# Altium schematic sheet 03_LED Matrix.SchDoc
size 772 x 495 mm
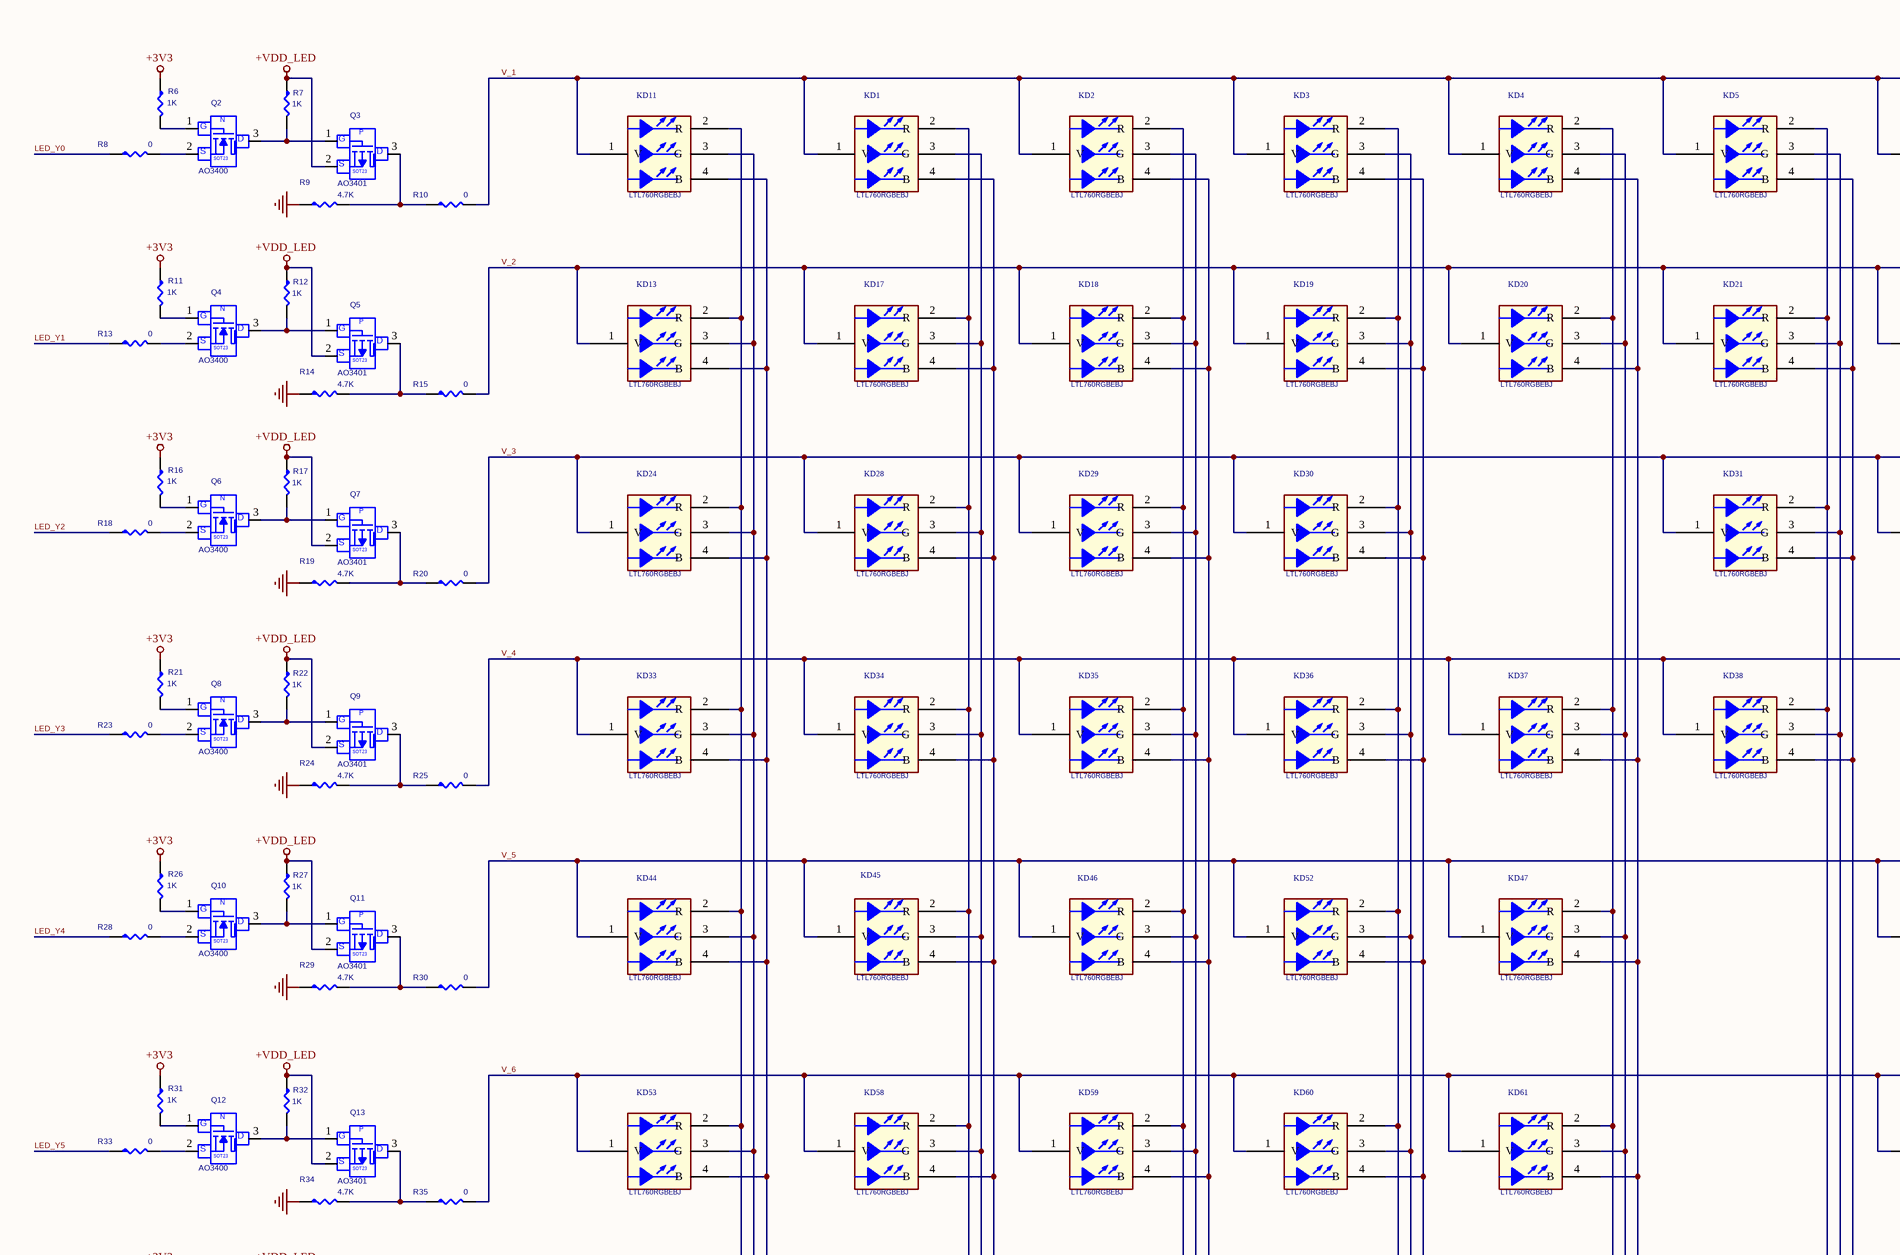
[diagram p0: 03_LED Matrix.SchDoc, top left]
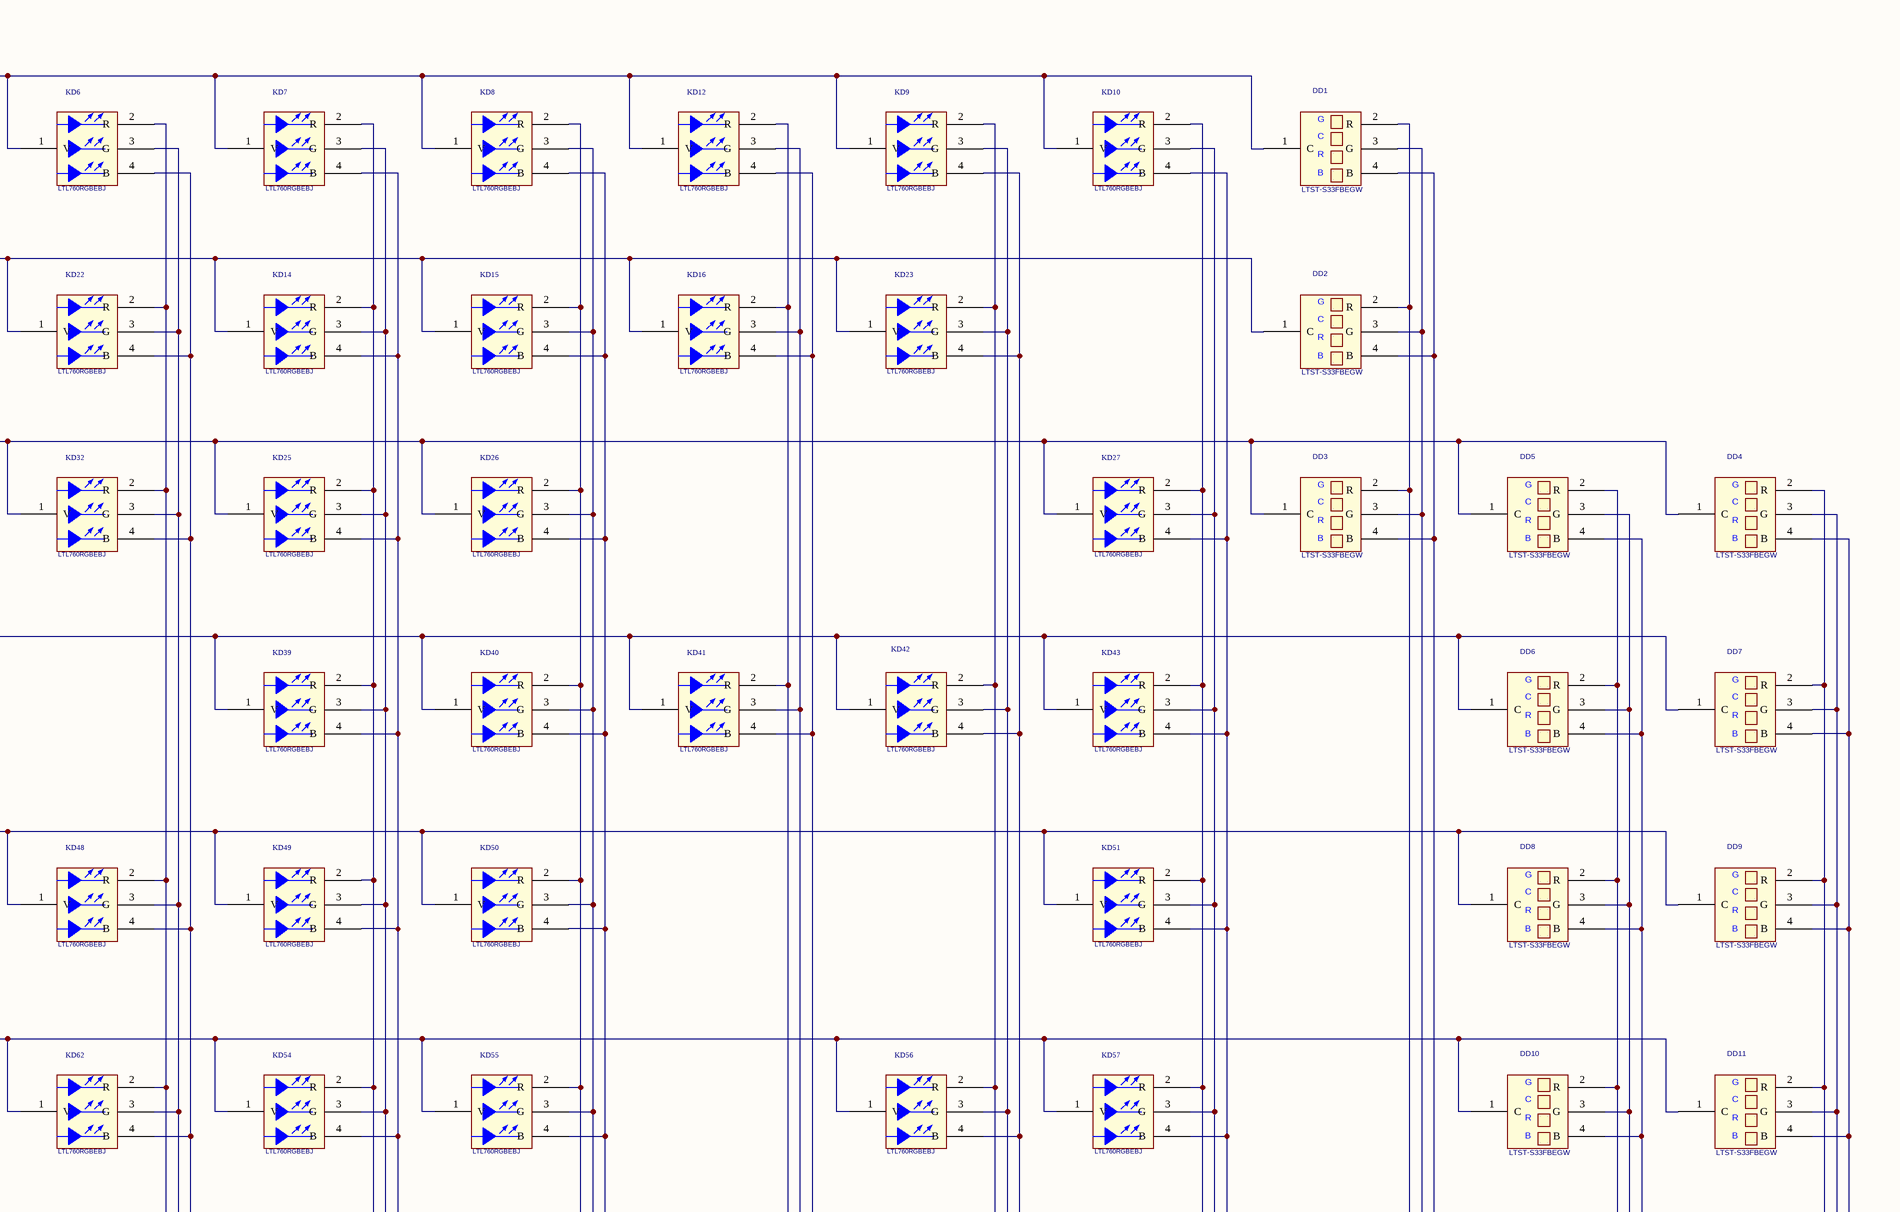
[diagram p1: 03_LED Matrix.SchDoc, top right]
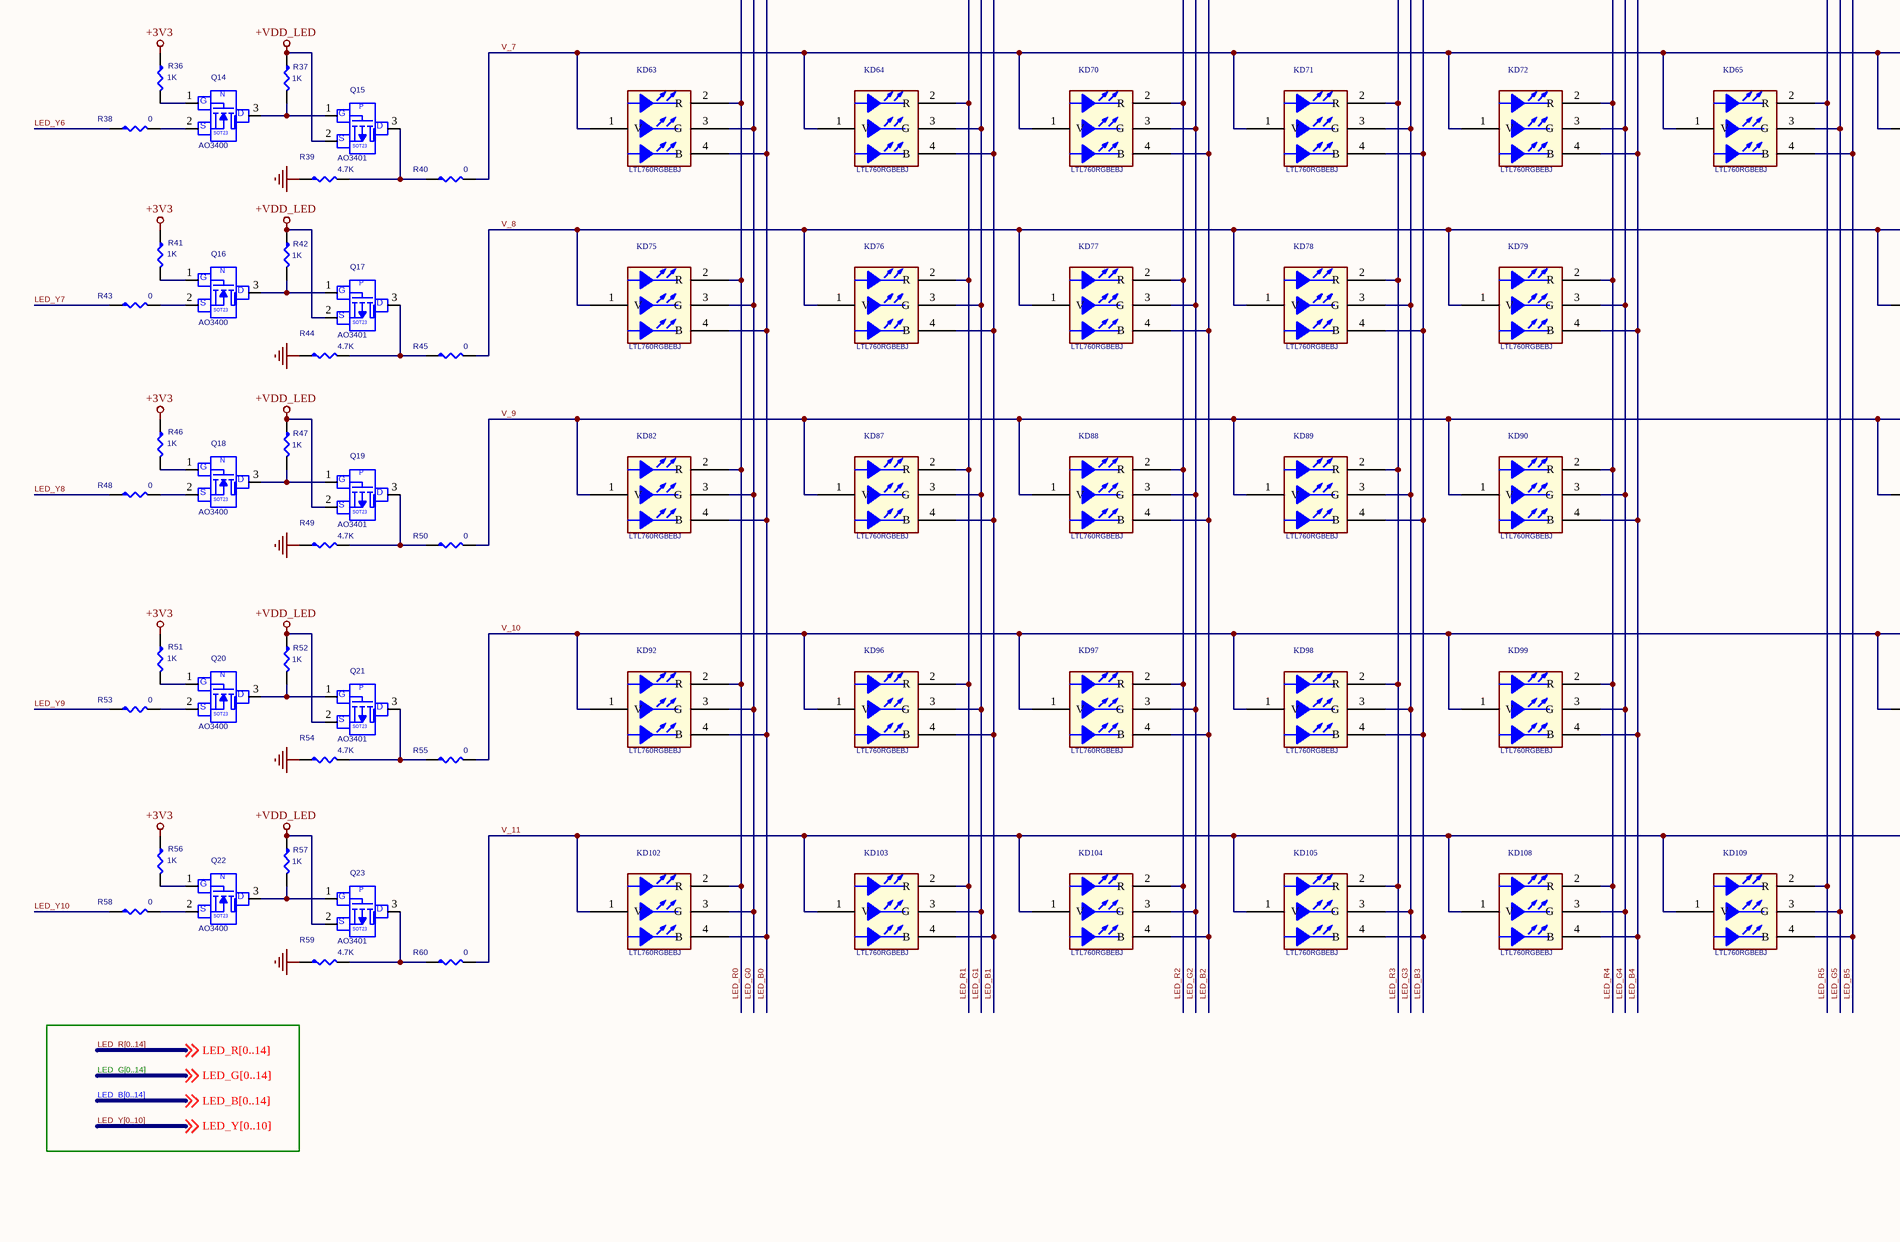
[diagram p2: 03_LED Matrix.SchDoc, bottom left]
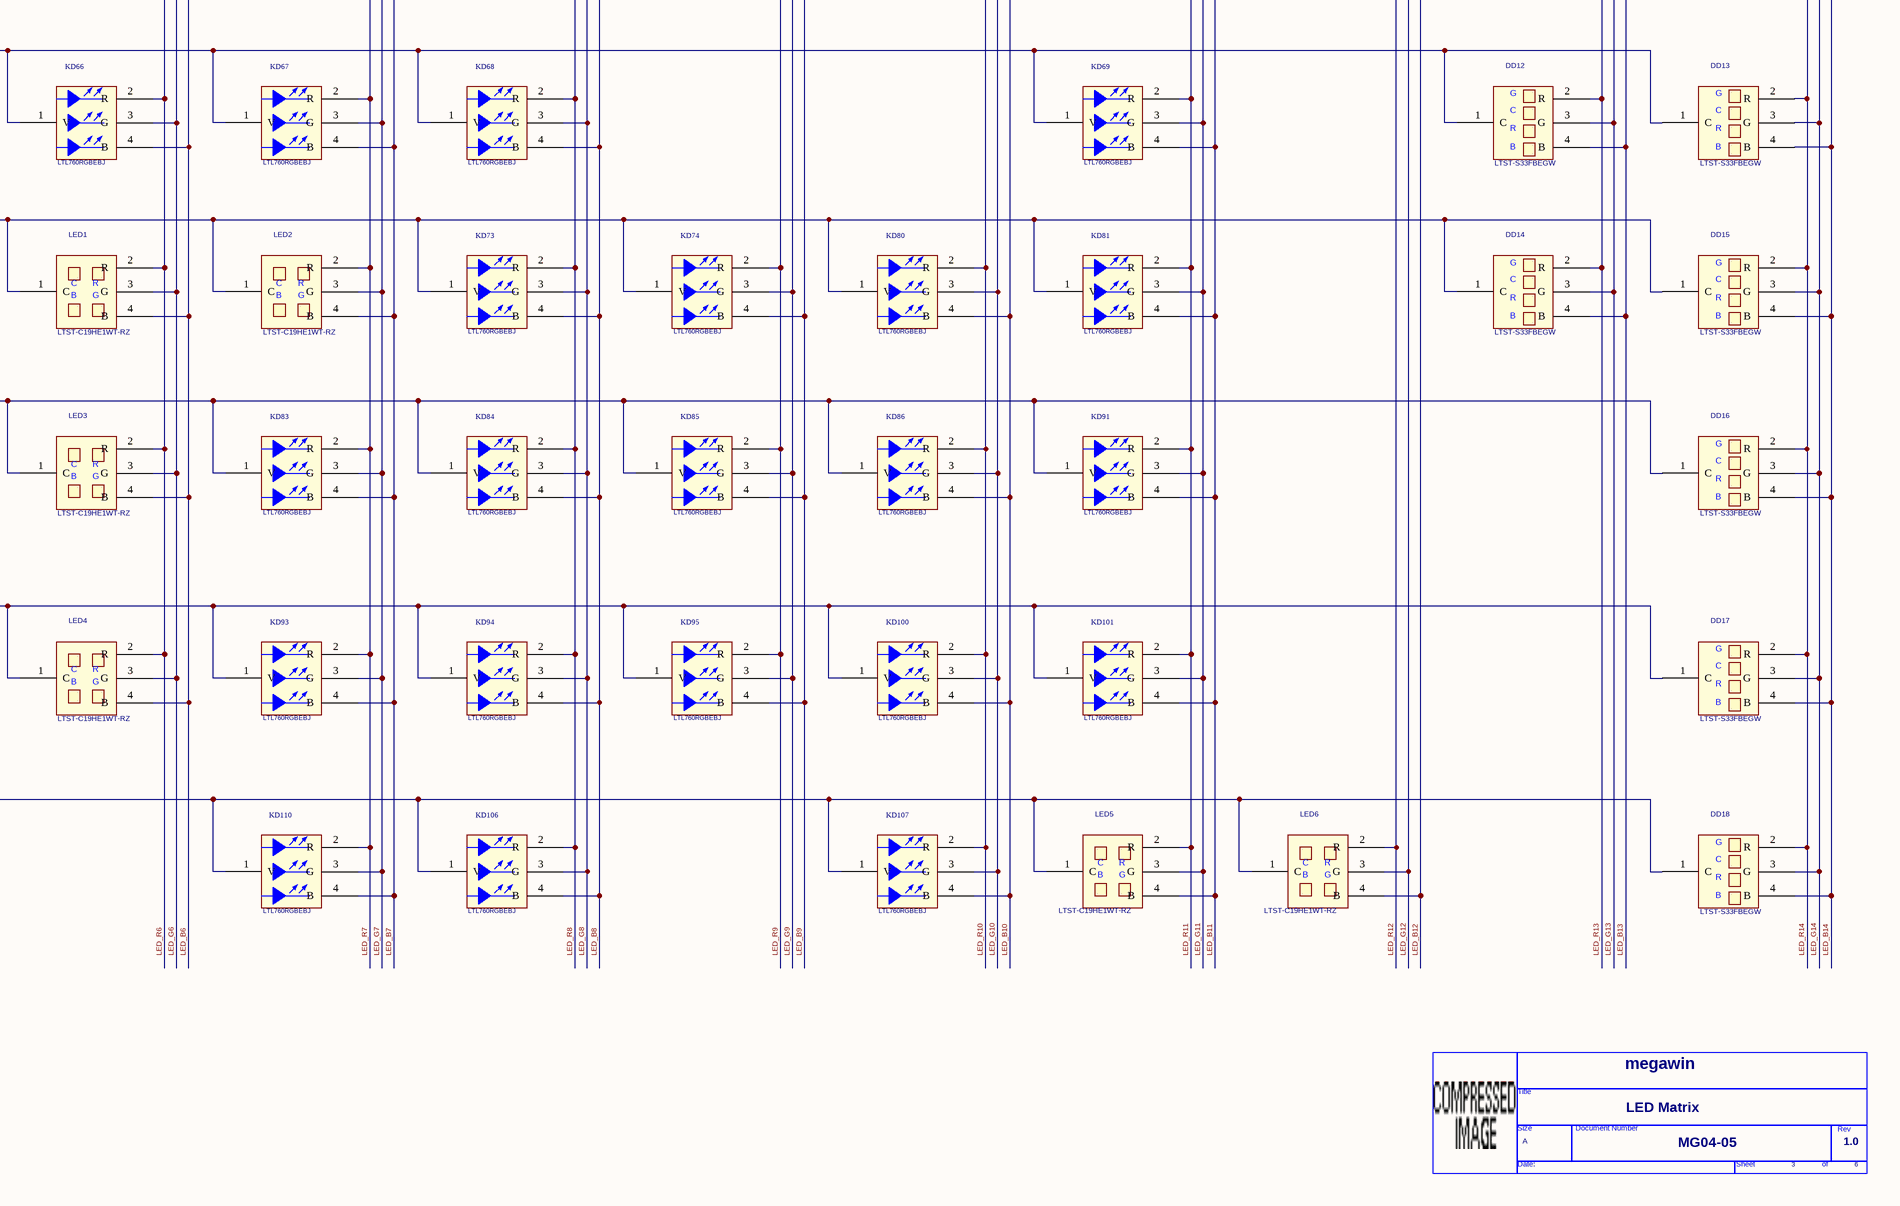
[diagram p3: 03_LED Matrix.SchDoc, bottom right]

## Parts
*  OrgName: megawin  Doc: MG04-05  RevCode: 1.0  Title: LED Matrix  Page Size: A  Page Number: 3  Page Count: 6  (hidden comment: TitleBlock_MegaWin)  (graphical)
DD1  LTST-S33FBEGW  [LED4P_SMD_3X1_CRGB]
DD2  LTST-S33FBEGW  [LED4P_SMD_3X1_CRGB]
DD3  LTST-S33FBEGW  [LED4P_SMD_3X1_CRGB]
DD4  LTST-S33FBEGW  [LED4P_SMD_3X1_CRGB]
DD5  LTST-S33FBEGW  [LED4P_SMD_3X1_CRGB]
DD6  LTST-S33FBEGW  [LED4P_SMD_3X1_CRGB]
DD7  LTST-S33FBEGW  [LED4P_SMD_3X1_CRGB]
DD8  LTST-S33FBEGW  [LED4P_SMD_3X1_CRGB]
DD9  LTST-S33FBEGW  [LED4P_SMD_3X1_CRGB]
DD10  LTST-S33FBEGW  [LED4P_SMD_3X1_CRGB]
DD11  LTST-S33FBEGW  [LED4P_SMD_3X1_CRGB]
DD12  LTST-S33FBEGW  [LED4P_SMD_3X1_CRGB]
DD13  LTST-S33FBEGW  [LED4P_SMD_3X1_CRGB]
DD14  LTST-S33FBEGW  [LED4P_SMD_3X1_CRGB]
DD15  LTST-S33FBEGW  [LED4P_SMD_3X1_CRGB]
DD16  LTST-S33FBEGW  [LED4P_SMD_3X1_CRGB]
DD17  LTST-S33FBEGW  [LED4P_SMD_3X1_CRGB]
DD18  LTST-S33FBEGW  [LED4P_SMD_3X1_CRGB]
KD1  LTL760RGBEBJ  [LED_3.5_CRGB]
KD2  LTL760RGBEBJ  [LED_3.5_CRGB]
KD3  LTL760RGBEBJ  [LED_3.5_CRGB]
KD4  LTL760RGBEBJ  [LED_3.5_CRGB]
KD5  LTL760RGBEBJ  [LED_3.5_CRGB]
KD6  LTL760RGBEBJ  [LED_3.5_CRGB]
KD7  LTL760RGBEBJ  [LED_3.5_CRGB]
KD8  LTL760RGBEBJ  [LED_3.5_CRGB]
KD9  LTL760RGBEBJ  [LED_3.5_CRGB]
KD10  LTL760RGBEBJ  [LED_3.5_CRGB]
KD11  LTL760RGBEBJ  [LED_3.5_CRGB]
KD12  LTL760RGBEBJ  [LED_3.5_CRGB]
KD13  LTL760RGBEBJ  [LED_3.5_CRGB]
KD14  LTL760RGBEBJ  [LED_3.5_CRGB]
KD15  LTL760RGBEBJ  [LED_3.5_CRGB]
KD16  LTL760RGBEBJ  [LED_3.5_CRGB]
KD17  LTL760RGBEBJ  [LED_3.5_CRGB]
KD18  LTL760RGBEBJ  [LED_3.5_CRGB]
KD19  LTL760RGBEBJ  [LED_3.5_CRGB]
KD20  LTL760RGBEBJ  [LED_3.5_CRGB]
KD21  LTL760RGBEBJ  [LED_3.5_CRGB]
KD22  LTL760RGBEBJ  [LED_3.5_CRGB]
KD23  LTL760RGBEBJ  [LED_3.5_CRGB]
KD24  LTL760RGBEBJ  [LED_3.5_CRGB]
KD25  LTL760RGBEBJ  [LED_3.5_CRGB]
KD26  LTL760RGBEBJ  [LED_3.5_CRGB]
KD27  LTL760RGBEBJ  [LED_3.5_CRGB]
KD28  LTL760RGBEBJ  [LED_3.5_CRGB]
KD29  LTL760RGBEBJ  [LED_3.5_CRGB]
KD30  LTL760RGBEBJ  [LED_3.5_CRGB]
KD31  LTL760RGBEBJ  [LED_3.5_CRGB]
KD32  LTL760RGBEBJ  [LED_3.5_CRGB]
KD33  LTL760RGBEBJ  [LED_3.5_CRGB]
KD34  LTL760RGBEBJ  [LED_3.5_CRGB]
KD35  LTL760RGBEBJ  [LED_3.5_CRGB]
KD36  LTL760RGBEBJ  [LED_3.5_CRGB]
KD37  LTL760RGBEBJ  [LED_3.5_CRGB]
KD38  LTL760RGBEBJ  [LED_3.5_CRGB]
KD39  LTL760RGBEBJ  [LED_3.5_CRGB]
KD40  LTL760RGBEBJ  [LED_3.5_CRGB]
KD41  LTL760RGBEBJ  [LED_3.5_CRGB]
KD42  LTL760RGBEBJ  [LED_3.5_CRGB]
KD43  LTL760RGBEBJ  [LED_3.5_CRGB]
KD44  LTL760RGBEBJ  [LED_3.5_CRGB]
KD45  LTL760RGBEBJ  [LED_3.5_CRGB]
KD46  LTL760RGBEBJ  [LED_3.5_CRGB]
KD47  LTL760RGBEBJ  [LED_3.5_CRGB]
KD48  LTL760RGBEBJ  [LED_3.5_CRGB]
KD49  LTL760RGBEBJ  [LED_3.5_CRGB]
KD50  LTL760RGBEBJ  [LED_3.5_CRGB]
KD51  LTL760RGBEBJ  [LED_3.5_CRGB]
KD52  LTL760RGBEBJ  [LED_3.5_CRGB]
KD53  LTL760RGBEBJ  [LED_3.5_CRGB]
KD54  LTL760RGBEBJ  [LED_3.5_CRGB]
KD55  LTL760RGBEBJ  [LED_3.5_CRGB]
KD56  LTL760RGBEBJ  [LED_3.5_CRGB]
KD57  LTL760RGBEBJ  [LED_3.5_CRGB]
KD58  LTL760RGBEBJ  [LED_3.5_CRGB]
KD59  LTL760RGBEBJ  [LED_3.5_CRGB]
KD60  LTL760RGBEBJ  [LED_3.5_CRGB]
KD61  LTL760RGBEBJ  [LED_3.5_CRGB]
KD62  LTL760RGBEBJ  [LED_3.5_CRGB]
KD63  LTL760RGBEBJ  [LED_3.5_CRGB]
KD64  LTL760RGBEBJ  [LED_3.5_CRGB]
KD65  LTL760RGBEBJ  [LED_3.5_CRGB]
KD66  LTL760RGBEBJ  [LED_3.5_CRGB]
KD67  LTL760RGBEBJ  [LED_3.5_CRGB]
KD68  LTL760RGBEBJ  [LED_3.5_CRGB]
KD69  LTL760RGBEBJ  [LED_3.5_CRGB]
KD70  LTL760RGBEBJ  [LED_3.5_CRGB]
KD71  LTL760RGBEBJ  [LED_3.5_CRGB]
KD72  LTL760RGBEBJ  [LED_3.5_CRGB]
KD73  LTL760RGBEBJ  [LED_3.5_CRGB]
KD74  LTL760RGBEBJ  [LED_3.5_CRGB]
KD75  LTL760RGBEBJ  [LED_3.5_CRGB]
KD76  LTL760RGBEBJ  [LED_3.5_CRGB]
KD77  LTL760RGBEBJ  [LED_3.5_CRGB]
KD78  LTL760RGBEBJ  [LED_3.5_CRGB]
KD79  LTL760RGBEBJ  [LED_3.5_CRGB]
KD80  LTL760RGBEBJ  [LED_3.5_CRGB]
KD81  LTL760RGBEBJ  [LED_3.5_CRGB]
KD82  LTL760RGBEBJ  [LED_3.5_CRGB]
KD83  LTL760RGBEBJ  [LED_3.5_CRGB]
KD84  LTL760RGBEBJ  [LED_3.5_CRGB]
KD85  LTL760RGBEBJ  [LED_3.5_CRGB]
KD86  LTL760RGBEBJ  [LED_3.5_CRGB]
KD87  LTL760RGBEBJ  [LED_3.5_CRGB]
KD88  LTL760RGBEBJ  [LED_3.5_CRGB]
KD89  LTL760RGBEBJ  [LED_3.5_CRGB]
KD90  LTL760RGBEBJ  [LED_3.5_CRGB]
KD91  LTL760RGBEBJ  [LED_3.5_CRGB]
KD92  LTL760RGBEBJ  [LED_3.5_CRGB]
KD93  LTL760RGBEBJ  [LED_3.5_CRGB]
KD94  LTL760RGBEBJ  [LED_3.5_CRGB]
KD95  LTL760RGBEBJ  [LED_3.5_CRGB]
KD96  LTL760RGBEBJ  [LED_3.5_CRGB]
KD97  LTL760RGBEBJ  [LED_3.5_CRGB]
KD98  LTL760RGBEBJ  [LED_3.5_CRGB]
KD99  LTL760RGBEBJ  [LED_3.5_CRGB]
KD100  LTL760RGBEBJ  [LED_3.5_CRGB]
KD101  LTL760RGBEBJ  [LED_3.5_CRGB]
KD102  LTL760RGBEBJ  [LED_3.5_CRGB]
KD103  LTL760RGBEBJ  [LED_3.5_CRGB]
KD104  LTL760RGBEBJ  [LED_3.5_CRGB]
KD105  LTL760RGBEBJ  [LED_3.5_CRGB]
KD106  LTL760RGBEBJ  [LED_3.5_CRGB]
KD107  LTL760RGBEBJ  [LED_3.5_CRGB]
KD108  LTL760RGBEBJ  [LED_3.5_CRGB]
KD109  LTL760RGBEBJ  [LED_3.5_CRGB]
KD110  LTL760RGBEBJ  [LED_3.5_CRGB]
LED1  LTST-C19HE1WT-RZ  [LED4P_SMD_1.6X1.6_CRGB]
LED2  LTST-C19HE1WT-RZ  [LED4P_SMD_1.6X1.6_CRGB]
LED3  LTST-C19HE1WT-RZ  [LED4P_SMD_1.6X1.6_CRGB]
LED4  LTST-C19HE1WT-RZ  [LED4P_SMD_1.6X1.6_CRGB]
LED5  LTST-C19HE1WT-RZ  [LED4P_SMD_1.6X1.6_CRGB]
LED6  LTST-C19HE1WT-RZ  [LED4P_SMD_1.6X1.6_CRGB]
Q2  AO3400  [SOT-23]
Q3  AO3401  [SOT-23]
Q4  AO3400  [SOT-23]
Q5  AO3401  [SOT-23]
Q6  AO3400  [SOT-23]
Q7  AO3401  [SOT-23]
Q8  AO3400  [SOT-23]
Q9  AO3401  [SOT-23]
Q10  AO3400  [SOT-23]
Q11  AO3401  [SOT-23]
Q12  AO3400  [SOT-23]
Q13  AO3401  [SOT-23]
Q14  AO3400  [SOT-23]
Q15  AO3401  [SOT-23]
Q16  AO3400  [SOT-23]
Q17  AO3401  [SOT-23]
Q18  AO3400  [SOT-23]
Q19  AO3401  [SOT-23]
Q20  AO3400  [SOT-23]
Q21  AO3401  [SOT-23]
Q22  AO3400  [SOT-23]
Q23  AO3401  [SOT-23]
R6  1K  [R-0603]
R7  1K  [R-0603]
R8  0  [R-0603]
R9  4.7K  [R-0603]
R10  0  [R-0603]
R11  1K  [R-0603]
R12  1K  [R-0603]
R13  0  [R-0603]
R14  4.7K  [R-0603]
R15  0  [R-0603]
R16  1K  [R-0603]
R17  1K  [R-0603]
R18  0  [R-0603]
R19  4.7K  [R-0603]
R20  0  [R-0603]
R21  1K  [R-0603]
R22  1K  [R-0603]
R23  0  [R-0603]
R24  4.7K  [R-0603]
R25  0  [R-0603]
R26  1K  [R-0603]
R27  1K  [R-0603]
R28  0  [R-0603]
R29  4.7K  [R-0603]
R30  0  [R-0603]
R31  1K  [R-0603]
R32  1K  [R-0603]
R33  0  [R-0603]
R34  4.7K  [R-0603]
R35  0  [R-0603]
R36  1K  [R-0603]
R37  1K  [R-0603]
R38  0  [R-0603]
R39  4.7K  [R-0603]
R40  0  [R-0603]
R41  1K  [R-0603]
R42  1K  [R-0603]
R43  0  [R-0603]
R44  4.7K  [R-0603]
R45  0  [R-0603]
R46  1K  [R-0603]
R47  1K  [R-0603]
R48  0  [R-0603]
R49  4.7K  [R-0603]
R50  0  [R-0603]
R51  1K  [R-0603]
R52  1K  [R-0603]
R53  0  [R-0603]
R54  4.7K  [R-0603]
R55  0  [R-0603]
R56  1K  [R-0603]
R57  1K  [R-0603]
R58  0  [R-0603]
R59  4.7K  [R-0603]
R60  0  [R-0603]

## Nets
+3V3: R6.1 R11.1 R16.1 R21.1 R26.1 R31.1 R36.1 R41.1 R46.1 R51.1 R56.1
+VDD_LED: Q3.2(S) Q5.2(S) Q7.2(S) Q9.2(S) Q11.2(S) Q13.2(S) Q15.2(S) Q17.2(S) Q19.2(S) Q21.2(S) Q23.2(S) R7.1 R12.1 R17.1 R22.1 R27.1 R32.1 R37.1 R42.1 R47.1 R52.1 R57.1
GND: R9.1 R14.1 R19.1 R24.1 R29.1 R34.1 R39.1 R44.1 R49.1 R54.1 R59.1
LED_B0: KD11.4(B) KD13.4(B) KD24.4(B) KD33.4(B) KD44.4(B) KD53.4(B) KD63.4(B) KD75.4(B) KD82.4(B) KD92.4(B) KD102.4(B)
LED_B1: KD1.4(B) KD17.4(B) KD28.4(B) KD34.4(B) KD45.4(B) KD58.4(B) KD64.4(B) KD76.4(B) KD87.4(B) KD96.4(B) KD103.4(B)
LED_B2: KD2.4(B) KD18.4(B) KD29.4(B) KD35.4(B) KD46.4(B) KD59.4(B) KD70.4(B) KD77.4(B) KD88.4(B) KD97.4(B) KD104.4(B)
LED_B3: KD3.4(B) KD19.4(B) KD30.4(B) KD36.4(B) KD52.4(B) KD60.4(B) KD71.4(B) KD78.4(B) KD89.4(B) KD98.4(B) KD105.4(B)
LED_B4: KD4.4(B) KD20.4(B) KD37.4(B) KD47.4(B) KD61.4(B) KD72.4(B) KD79.4(B) KD90.4(B) KD99.4(B) KD108.4(B)
LED_B5: KD5.4(B) KD21.4(B) KD31.4(B) KD38.4(B) KD65.4(B) KD109.4(B)
LED_B6: KD6.4(B) KD22.4(B) KD32.4(B) KD48.4(B) KD62.4(B) KD66.4(B) LED1.4(B) LED3.4(B) LED4.4(B)
LED_B7: KD7.4(B) KD14.4(B) KD25.4(B) KD39.4(B) KD49.4(B) KD54.4(B) KD67.4(B) KD83.4(B) KD93.4(B) KD110.4(B) LED2.4(B)
LED_B8: KD8.4(B) KD15.4(B) KD26.4(B) KD40.4(B) KD50.4(B) KD55.4(B) KD68.4(B) KD73.4(B) KD84.4(B) KD94.4(B) KD106.4(B)
LED_B9: KD12.4(B) KD16.4(B) KD41.4(B) KD74.4(B) KD85.4(B) KD95.4(B)
LED_B10: KD9.4(B) KD23.4(B) KD42.4(B) KD56.4(B) KD80.4(B) KD86.4(B) KD100.4(B) KD107.4(B)
LED_B11: KD10.4(B) KD27.4(B) KD43.4(B) KD51.4(B) KD57.4(B) KD69.4(B) KD81.4(B) KD91.4(B) KD101.4(B) LED5.4(B)
LED_B12: DD1.4(B) DD2.4(B) DD3.4(B) LED6.4(B)
LED_B13: DD5.4(B) DD6.4(B) DD8.4(B) DD10.4(B) DD12.4(B) DD14.4(B)
LED_B14: DD4.4(B) DD7.4(B) DD9.4(B) DD11.4(B) DD13.4(B) DD15.4(B) DD16.4(B) DD17.4(B) DD18.4(B)
LED_G0: KD11.3(G) KD13.3(G) KD24.3(G) KD33.3(G) KD44.3(G) KD53.3(G) KD63.3(G) KD75.3(G) KD82.3(G) KD92.3(G) KD102.3(G)
LED_G1: KD1.3(G) KD17.3(G) KD28.3(G) KD34.3(G) KD45.3(G) KD58.3(G) KD64.3(G) KD76.3(G) KD87.3(G) KD96.3(G) KD103.3(G)
LED_G2: KD2.3(G) KD18.3(G) KD29.3(G) KD35.3(G) KD46.3(G) KD59.3(G) KD70.3(G) KD77.3(G) KD88.3(G) KD97.3(G) KD104.3(G)
LED_G3: KD3.3(G) KD19.3(G) KD30.3(G) KD36.3(G) KD52.3(G) KD60.3(G) KD71.3(G) KD78.3(G) KD89.3(G) KD98.3(G) KD105.3(G)
LED_G4: KD4.3(G) KD20.3(G) KD37.3(G) KD47.3(G) KD61.3(G) KD72.3(G) KD79.3(G) KD90.3(G) KD99.3(G) KD108.3(G)
LED_G5: KD5.3(G) KD21.3(G) KD31.3(G) KD38.3(G) KD65.3(G) KD109.3(G)
LED_G6: KD6.3(G) KD22.3(G) KD32.3(G) KD48.3(G) KD62.3(G) KD66.3(G) LED1.3(G) LED3.3(G) LED4.3(G)
LED_G7: KD7.3(G) KD14.3(G) KD25.3(G) KD39.3(G) KD49.3(G) KD54.3(G) KD67.3(G) KD83.3(G) KD93.3(G) KD110.3(G) LED2.3(G)
LED_G8: KD8.3(G) KD15.3(G) KD26.3(G) KD40.3(G) KD50.3(G) KD55.3(G) KD68.3(G) KD73.3(G) KD84.3(G) KD94.3(G) KD106.3(G)
LED_G9: KD12.3(G) KD16.3(G) KD41.3(G) KD74.3(G) KD85.3(G) KD95.3(G)
LED_G10: KD9.3(G) KD23.3(G) KD42.3(G) KD56.3(G) KD80.3(G) KD86.3(G) KD100.3(G) KD107.3(G)
LED_G11: KD10.3(G) KD27.3(G) KD43.3(G) KD51.3(G) KD57.3(G) KD69.3(G) KD81.3(G) KD91.3(G) KD101.3(G) LED5.3(G)
LED_G12: DD1.3(G) DD2.3(G) DD3.3(G) LED6.3(G)
LED_G13: DD5.3(G) DD6.3(G) DD8.3(G) DD10.3(G) DD12.3(G) DD14.3(G)
LED_G14: DD4.3(G) DD7.3(G) DD9.3(G) DD11.3(G) DD13.3(G) DD15.3(G) DD16.3(G) DD17.3(G) DD18.3(G)
LED_R0: KD11.2(R) KD13.2(R) KD24.2(R) KD33.2(R) KD44.2(R) KD53.2(R) KD63.2(R) KD75.2(R) KD82.2(R) KD92.2(R) KD102.2(R)
LED_R1: KD1.2(R) KD17.2(R) KD28.2(R) KD34.2(R) KD45.2(R) KD58.2(R) KD64.2(R) KD76.2(R) KD87.2(R) KD96.2(R) KD103.2(R)
LED_R2: KD2.2(R) KD18.2(R) KD29.2(R) KD35.2(R) KD46.2(R) KD59.2(R) KD70.2(R) KD77.2(R) KD88.2(R) KD97.2(R) KD104.2(R)
LED_R3: KD3.2(R) KD19.2(R) KD30.2(R) KD36.2(R) KD52.2(R) KD60.2(R) KD71.2(R) KD78.2(R) KD89.2(R) KD98.2(R) KD105.2(R)
LED_R4: KD4.2(R) KD20.2(R) KD37.2(R) KD47.2(R) KD61.2(R) KD72.2(R) KD79.2(R) KD90.2(R) KD99.2(R) KD108.2(R)
LED_R5: KD5.2(R) KD21.2(R) KD31.2(R) KD38.2(R) KD65.2(R) KD109.2(R)
LED_R6: KD6.2(R) KD22.2(R) KD32.2(R) KD48.2(R) KD62.2(R) KD66.2(R) LED1.2(R) LED3.2(R) LED4.2(R)
LED_R7: KD7.2(R) KD14.2(R) KD25.2(R) KD39.2(R) KD49.2(R) KD54.2(R) KD67.2(R) KD83.2(R) KD93.2(R) KD110.2(R) LED2.2(R)
LED_R8: KD8.2(R) KD15.2(R) KD26.2(R) KD40.2(R) KD50.2(R) KD55.2(R) KD68.2(R) KD73.2(R) KD84.2(R) KD94.2(R) KD106.2(R)
LED_R9: KD12.2(R) KD16.2(R) KD41.2(R) KD74.2(R) KD85.2(R) KD95.2(R)
LED_R10: KD9.2(R) KD23.2(R) KD42.2(R) KD56.2(R) KD80.2(R) KD86.2(R) KD100.2(R) KD107.2(R)
LED_R11: KD10.2(R) KD27.2(R) KD43.2(R) KD51.2(R) KD57.2(R) KD69.2(R) KD81.2(R) KD91.2(R) KD101.2(R) LED5.2(R)
LED_R12: DD1.2(R) DD2.2(R) DD3.2(R) LED6.2(R)
LED_R13: DD5.2(R) DD6.2(R) DD8.2(R) DD10.2(R) DD12.2(R) DD14.2(R)
LED_R14: DD4.2(R) DD7.2(R) DD9.2(R) DD11.2(R) DD13.2(R) DD15.2(R) DD16.2(R) DD17.2(R) DD18.2(R)
LED_Y0: R8.1
LED_Y1: R13.1
LED_Y2: R18.1
LED_Y3: R23.1
LED_Y4: R28.1
LED_Y5: R33.1
LED_Y6: R38.1
LED_Y7: R43.1
LED_Y8: R48.1
LED_Y9: R53.1
LED_Y10: R58.1
V_1: DD1.1(C) KD1.1(V) KD2.1(V) KD3.1(V) KD4.1(V) KD5.1(V) KD6.1(V) KD7.1(V) KD8.1(V) KD9.1(V) KD10.1(V) KD11.1(V) KD12.1(V) R10.2
V_2: DD2.1(C) KD13.1(V) KD14.1(V) KD15.1(V) KD16.1(V) KD17.1(V) KD18.1(V) KD19.1(V) KD20.1(V) KD21.1(V) KD22.1(V) KD23.1(V) R15.2
V_3: DD3.1(C) DD4.1(C) DD5.1(C) KD24.1(V) KD25.1(V) KD26.1(V) KD27.1(V) KD28.1(V) KD29.1(V) KD30.1(V) KD31.1(V) KD32.1(V) R20.2
V_4: DD6.1(C) DD7.1(C) KD33.1(V) KD34.1(V) KD35.1(V) KD36.1(V) KD37.1(V) KD38.1(V) KD39.1(V) KD40.1(V) KD41.1(V) KD42.1(V) KD43.1(V) R25.2
V_5: DD8.1(C) DD9.1(C) KD44.1(V) KD45.1(V) KD46.1(V) KD47.1(V) KD48.1(V) KD49.1(V) KD50.1(V) KD51.1(V) KD52.1(V) R30.2
V_6: DD10.1(C) DD11.1(C) KD53.1(V) KD54.1(V) KD55.1(V) KD56.1(V) KD57.1(V) KD58.1(V) KD59.1(V) KD60.1(V) KD61.1(V) KD62.1(V) R35.2
V_7: DD12.1(C) DD13.1(C) KD63.1(V) KD64.1(V) KD65.1(V) KD66.1(V) KD67.1(V) KD68.1(V) KD69.1(V) KD70.1(V) KD71.1(V) KD72.1(V) R40.2
V_8: DD14.1(C) DD15.1(C) KD73.1(V) KD74.1(V) KD75.1(V) KD76.1(V) KD77.1(V) KD78.1(V) KD79.1(V) KD80.1(V) KD81.1(V) LED1.1(C) LED2.1(C) R45.2
V_9: DD16.1(C) KD82.1(V) KD83.1(V) KD84.1(V) KD85.1(V) KD86.1(V) KD87.1(V) KD88.1(V) KD89.1(V) KD90.1(V) KD91.1(V) LED3.1(C) R50.2
V_10: DD17.1(C) KD92.1(V) KD93.1(V) KD94.1(V) KD95.1(V) KD96.1(V) KD97.1(V) KD98.1(V) KD99.1(V) KD100.1(V) KD101.1(V) LED4.1(C) R55.2
V_11: DD18.1(C) KD102.1(V) KD103.1(V) KD104.1(V) KD105.1(V) KD106.1(V) KD107.1(V) KD108.1(V) KD109.1(V) KD110.1(V) LED5.1(C) LED6.1(C) R60.2
NetQ2_1: Q2.1(G) R6.2
NetQ2_2: Q2.2(S) R8.2
NetQ2_3: Q2.3(D) Q3.1(G) R7.2
NetQ3_3: Q3.3(D) R9.2 R10.1
NetQ4_1: Q4.1(G) R11.2
NetQ4_2: Q4.2(S) R13.2
NetQ4_3: Q4.3(D) Q5.1(G) R12.2
NetQ5_3: Q5.3(D) R14.2 R15.1
NetQ6_1: Q6.1(G) R16.2
NetQ6_2: Q6.2(S) R18.2
NetQ6_3: Q6.3(D) Q7.1(G) R17.2
NetQ7_3: Q7.3(D) R19.2 R20.1
NetQ8_1: Q8.1(G) R21.2
NetQ8_2: Q8.2(S) R23.2
NetQ8_3: Q8.3(D) Q9.1(G) R22.2
NetQ9_3: Q9.3(D) R24.2 R25.1
NetQ10_1: Q10.1(G) R26.2
NetQ10_2: Q10.2(S) R28.2
NetQ10_3: Q10.3(D) Q11.1(G) R27.2
NetQ11_3: Q11.3(D) R29.2 R30.1
NetQ12_1: Q12.1(G) R31.2
NetQ12_2: Q12.2(S) R33.2
NetQ12_3: Q12.3(D) Q13.1(G) R32.2
NetQ13_3: Q13.3(D) R34.2 R35.1
NetQ14_1: Q14.1(G) R36.2
NetQ14_2: Q14.2(S) R38.2
NetQ14_3: Q14.3(D) Q15.1(G) R37.2
NetQ15_3: Q15.3(D) R39.2 R40.1
NetQ16_1: Q16.1(G) R41.2
NetQ16_2: Q16.2(S) R43.2
NetQ16_3: Q16.3(D) Q17.1(G) R42.2
NetQ17_3: Q17.3(D) R44.2 R45.1
NetQ18_1: Q18.1(G) R46.2
NetQ18_2: Q18.2(S) R48.2
NetQ18_3: Q18.3(D) Q19.1(G) R47.2
NetQ19_3: Q19.3(D) R49.2 R50.1
NetQ20_1: Q20.1(G) R51.2
NetQ20_2: Q20.2(S) R53.2
NetQ20_3: Q20.3(D) Q21.1(G) R52.2
NetQ21_3: Q21.3(D) R54.2 R55.1
NetQ22_1: Q22.1(G) R56.2
NetQ22_2: Q22.2(S) R58.2
NetQ22_3: Q22.3(D) Q23.1(G) R57.2
NetQ23_3: Q23.3(D) R59.2 R60.1

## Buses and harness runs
bus LED_B[0..14]
bus LED_G[0..14]
bus LED_R[0..14]
bus LED_Y[0..10]

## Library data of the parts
DD1-DD18 = LED-4P-CRGB3
KD1-KD110 = LED-4P-CRGB
LED1-LED6 = LED-4P-CRGB2
Q2 Q4 Q6 Q8 Q10 Q12 Q14 Q16 Q18 Q20 Q22 = MOS-N-SOT23
Q3 Q5 Q7 Q9 Q11 Q13 Q15 Q17 Q19 Q21 Q23 = MOS-P-SOT23
R6-R60 = RES: Opt-Part: _; New PN: R11-0560013; New Description: R,resistor,56ohm/5%/1/10W,0603; CLASS: DISCRETE; Asm Comm: 5010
